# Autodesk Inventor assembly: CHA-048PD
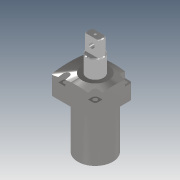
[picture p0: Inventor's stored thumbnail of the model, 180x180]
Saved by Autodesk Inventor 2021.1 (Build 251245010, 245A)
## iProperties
Created: 2018-12
Part Number: CHA-048PD
Description: STEP AP214
Document SubType Name: Assembly
Designer: user
Sending System: SolidWorks 2016
Preprocessor: SwSTEP 2.0
Title: CHA-048PD.STEP
Revision Number: ÈÎºÎ
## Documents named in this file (4)
- D:\Vault_2016\Projekty\Clamptek\Hydraulic\Dociski Hydrauliczne\Obrotowe\CHA-P\Inventor\CHA-048PD\CHA-048PD.iam
- D:\Vault_2016\Projekty\Clamptek\Hydraulic\Dociski Hydrauliczne\Obrotowe\CHA-P\Inventor\CHA-048PD\CHA-048P(BT).ipt
- D:\Vault_2016\Projekty\Clamptek\Hydraulic\Dociski Hydrauliczne\Obrotowe\CHA-P\Inventor\CHA-048PD\¶ÂÍ·G8-1.ipt
- D:\Vault_2016\Projekty\Clamptek\Hydraulic\Dociski Hydrauliczne\Obrotowe\CHA-P\Inventor\CHA-048PD\CHA-048PD(HSG).ipt
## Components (4 placed, 4 different names)
1. CHA-048P(BT)_1
2. ¶ÂÍ·G8-1_2
3. ¶ÂÍ·G8-1_3
4. CHA-048PD(HSG)_4
